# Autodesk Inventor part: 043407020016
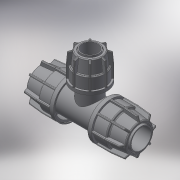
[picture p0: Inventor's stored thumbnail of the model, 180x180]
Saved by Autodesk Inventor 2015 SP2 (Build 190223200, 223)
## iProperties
Created: 2017-08
Part Number: 043407020016
Material: Generic
Description: PLASSON IRRIFIT REDUCING TEE 20-16-20
Document SubType Name: Modeling
Designer: KIM
Density: 1 g/cm^3
Appearance: Default
Author: KIM
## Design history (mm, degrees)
derived "043407.ipt"
feature "Solid1::043407.ipt"
tag "TaggingFeature1"
body "Solid1"
other parameters: "d5" = 34.2, "d6" = 17.1, "d10" = 39, "d22" = 28, "d24" = 3.8, "d25" = 35.1, "d26" = 31.2, "d31" = 1, "d49" = 1.95, "d50" = 0, "d58" = 0.6, "d61" = 360 deg, "d78" = 6 deg, "d80" = 22, "d81" = 51.5, "d82" = 2.85, "d84" = 5 deg, "d85" = 70 deg, "d86" = 37.05, "d87" = 0.95, "d88" = 0, "d89" = 33.15, "d90" = 9.5, "d91" = 0, "d132" = 53, "d152" = 16, "d153" = 17.6, "d154" = 2.4, "d155" = 27.2, "d156" = 6 deg, "d157" = 34, "d158" = 12.8, "d159" = 28.8, "d160" = 3.2, "d161" = 30.6, "d162" = 22.4, "d164" = 0.8, "d165" = 5 deg, "d166" = 70 deg, "d167" = 1.7, "d168" = 0, "d169" = 0.48, "d171" = 360 deg, "d174" = 32.3, "d175" = 0.8, "d176" = 0, "d177" = 28.9, "d178" = 8, "d179" = 0, "E_" = 39, "H_" = 103, "l_" = 19, "E_1" = 34, "A_" = 53, "l_1" = 16, "d_1" = 16, "d146" = 39, "d148" = 53, "d149" = 19, "d150" = 103
